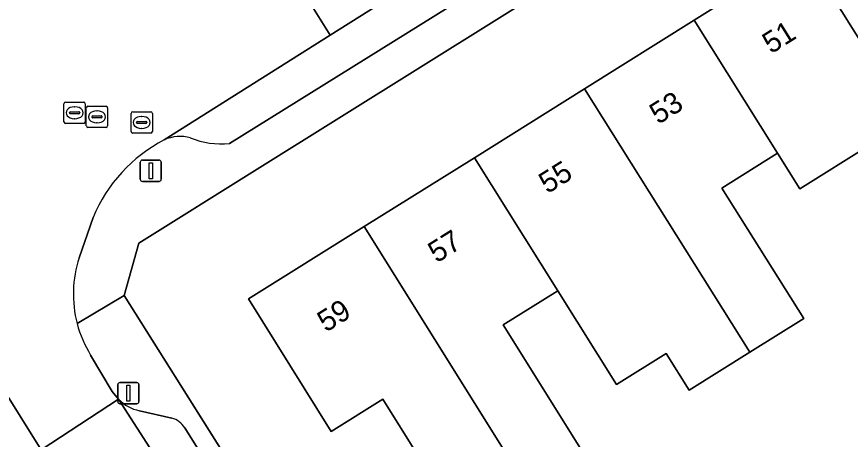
# Model space of a CAD drawing. Extents: x 159352 to 160617, y 385888 to 387323.
# Drawn here: x 159671.45 to 159710.67, y 386028.96 to 386048.83 of the extents above; entities that cross this region are included whole.
import ezdxf

# ---------------------------------------------------------------- set-up
doc = ezdxf.new("R2010")
doc.units = 0
for name, color, linetype in [('IMGEO_Erf', 7, 'Continuous'), ('IMGEO_Kolk', 7, 'Continuous'), ('IMGEO_Lichtmast', 7, 'Continuous'), ('IMGEO_Muur', 7, 'Continuous'), ('IMGEO_Pand', 7, 'Continuous'), ('IMGEO_Pand_nummerreeks', 7, 'Continuous'), ('IMGEO_Parkeervlak_open', 7, 'Continuous'), ('IMGEO_Rijbaan_lokaal_open', 7, 'Continuous'), ('IMGEO_Rioolput', 7, 'Continuous'), ('IMGEO_Voetpad_open', 7, 'Continuous')]:
    doc.layers.add(name, color=color, linetype=linetype)

msp = doc.modelspace()

# ---------------------------------------------------------------- linework, layer by layer
at = {"layer": 'IMGEO_Erf'}
msp.add_lwpolyline([(159733.186, 386035.211), (159730.405, 386039.383), (159739.998, 386045.377), (159726.053, 386067.427), (159724.652, 386067.823), (159682.76, 386041.661), (159677.195, 386038.177), (159676.499, 386035.726), (159692.861, 386009.756), (159693.588, 386010.224), (159695.905, 386011.714), (159692.99, 386016.431), (159699.422, 386020.406), (159702.337, 386015.688), (159707.722, 386019.015), (159705.988, 386021.823), (159710.701, 386024.734), (159712.435, 386021.927)], close=True, dxfattribs=at)
for points in [[(159692.572, 386024.604), (159688.668, 386030.843), (159686.251, 386029.331), (159682.354, 386035.559), (159687.801, 386038.964), (159692.982, 386042.203), (159698.161, 386045.441), (159703.328, 386048.671), (159708.502, 386051.905), (159713.682, 386055.143)], [(159711.6, 386042.813), (159708.294, 386040.745), (159707.246, 386042.417), (159704.617, 386040.772), (159708.473, 386034.64), (159705.947, 386033.06), (159703.085, 386031.27), (159701.997, 386033), (159699.669, 386031.543), (159696.906, 386035.948), (159694.342, 386034.344), (159698.765, 386027.275)]]:
    msp.add_lwpolyline(points, dxfattribs=at)
at = {"layer": 'IMGEO_Kolk'}
for p, q in [((159673.674, 386043.887), (159673.674, 386044.739)), ((159673.749, 386044.813), (159674.601, 386044.813)), ((159674.162, 386044.593), (159674.187, 386044.593)), ((159674.675, 386044.739), (159674.675, 386043.887)), ((159673.933, 386044.307), (159673.933, 386044.319)), ((159674.371, 386044.27), (159673.973, 386044.27)), ((159673.976, 386044.356), (159674.374, 386044.356)), ((159674.417, 386044.319), (159674.417, 386044.307)), ((159674.601, 386043.813), (159673.749, 386043.813)), ((159674.185, 386044.033), (159674.16, 386044.033))]:
    msp.add_line(p, q, dxfattribs=at)
for points in [[(159673.674, 386043.887), (159673.674, 386044.739)], [(159673.749, 386044.813), (159674.601, 386044.813)], [(159674.675, 386044.739), (159674.675, 386043.887)], [(159674.601, 386043.813), (159673.749, 386043.813)]]:
    msp.add_lwpolyline(points, dxfattribs=at)
for centre, radius, start, end in [((159673.751, 386044.737), 0.0765, 91.552, 178.448), ((159673.751, 386044.737), 0.0765, 91.552, 178.448), ((159674.599, 386044.737), 0.0765, 1.552, 88.448), ((159674.599, 386044.737), 0.0765, 1.552, 88.448), ((159673.973, 386044.316), 0.0403, 85.8775, 175.7526), ((159673.97, 386044.306), 0.0366, 178.938, 274.7102), ((159674.374, 386044.313), 0.043, 264.8664, 352.4533), ((159674.378, 386044.318), 0.0386, 1.7309, 96.639), ((159673.751, 386043.889), 0.0765, 181.552, 268.448), ((159673.751, 386043.889), 0.0765, 181.552, 268.448), ((159674.599, 386043.889), 0.0765, 271.552, 358.448), ((159674.599, 386043.889), 0.0765, 271.552, 358.448)]:
    msp.add_arc(centre, radius, start, end, dxfattribs=at)
for centre, major_axis, ratio, start_param, end_param in [((159674.161, 386044.313), (-0.387, 0.002), 0.722429, 4.712389, 7.853982), ((159674.186, 386044.313), (-0.39, 0.002), 0.717154, 1.570796, 4.712389)]:
    msp.add_ellipse(centre, major_axis=major_axis, ratio=ratio, start_param=start_param, end_param=end_param, dxfattribs=at)
at = {"layer": 'IMGEO_Lichtmast'}
for p, q in [((159677.262, 386041.187), (159677.262, 386041.987)), ((159677.262, 386041.987), (159677.262, 386041.187)), ((159677.362, 386042.087), (159678.152, 386042.087)), ((159678.152, 386042.087), (159677.362, 386042.087)), ((159678.252, 386041.987), (159678.252, 386041.187)), ((159678.252, 386041.187), (159678.252, 386041.987)), ((159678.152, 386041.087), (159677.362, 386041.087)), ((159677.362, 386041.087), (159678.152, 386041.087)), ((159676.307, 386031.632), (159677.097, 386031.632)), ((159677.097, 386031.632), (159676.307, 386031.632)), ((159676.207, 386030.732), (159676.207, 386031.532)), ((159676.207, 386031.532), (159676.207, 386030.732)), ((159677.197, 386031.532), (159677.197, 386030.732)), ((159677.197, 386030.732), (159677.197, 386031.532)), ((159677.097, 386030.632), (159676.307, 386030.632)), ((159676.307, 386030.632), (159677.097, 386030.632))]:
    msp.add_line(p, q, dxfattribs=at)
for points in [[(159677.682, 386041.962), (159677.832, 386041.962), (159677.832, 386041.212), (159677.682, 386041.212), (159677.682, 386041.962)], [(159676.627, 386031.507), (159676.777, 386031.507), (159676.777, 386030.757), (159676.627, 386030.757), (159676.627, 386031.507)]]:
    msp.add_lwpolyline(points, dxfattribs=at)
for centre, start, end in [((159677.362, 386041.987), 90, 180), ((159677.362, 386041.987), 90, 180), ((159678.152, 386041.987), 0, 90), ((159678.152, 386041.987), 360, 90), ((159677.362, 386041.187), 180, 270), ((159677.362, 386041.187), 180, 270), ((159678.152, 386041.187), 270, 0), ((159678.152, 386041.187), 270, 0), ((159676.307, 386031.532), 90, 180), ((159676.307, 386031.532), 90, 180), ((159677.097, 386031.532), 0, 90), ((159677.097, 386031.532), 360, 90), ((159676.307, 386030.732), 180, 270), ((159676.307, 386030.732), 180, 270), ((159677.097, 386030.732), 270, 0), ((159677.097, 386030.732), 270, 0)]:
    msp.add_arc(centre, 0.1, start, end, dxfattribs=at)
at = {"layer": 'IMGEO_Muur'}
msp.add_lwpolyline([(159676.499, 386035.726), (159692.838, 386009.794)], dxfattribs=at)
at = {"layer": 'IMGEO_Pand'}
for points in [[(159713.682, 386055.143), (159708.502, 386051.905), (159713.466, 386043.98), (159713.984, 386043.152), (159713.74, 386042.999), (159715.63, 386039.982), (159717.73, 386041.298), (159715.841, 386044.315), (159719.171, 386046.4)], [(159708.502, 386051.905), (159703.328, 386048.671), (159707.246, 386042.417), (159708.294, 386040.745), (159711.6, 386042.813), (159715.372, 386036.791), (159716.992, 386037.806), (159715.63, 386039.982), (159713.74, 386042.999), (159713.984, 386043.152), (159713.466, 386043.98)], [(159703.328, 386048.671), (159698.161, 386045.441), (159705.947, 386033.06), (159708.473, 386034.64), (159704.617, 386040.772), (159707.246, 386042.417)], [(159696.906, 386035.948), (159699.669, 386031.543), (159701.997, 386033), (159703.085, 386031.27), (159705.947, 386033.06), (159698.161, 386045.441), (159692.982, 386042.203)], [(159692.982, 386042.203), (159687.801, 386038.964), (159696.144, 386025.636), (159698.765, 386027.275), (159694.342, 386034.344), (159696.906, 386035.948)], [(159687.801, 386038.964), (159682.354, 386035.559), (159686.251, 386029.331), (159688.668, 386030.843), (159692.572, 386024.604), (159695.412, 386026.381), (159695.953, 386025.516), (159696.144, 386025.636)]]:
    msp.add_lwpolyline(points, close=True, dxfattribs=at)
at = {"layer": 'IMGEO_Parkeervlak_open'}
for points in [[(159717.543, 386067.695), (159686.194, 386047.956), (159678.382, 386043.037)], [(159681.467, 386042.865), (159702.746, 386056.105), (159715.811, 386064.272)], [(159676.243, 386030.847), (159688.08, 386012.469)], [(159678.751, 386029.956), (159677.22, 386030.307)], [(159688.07, 386015.556), (159679.356, 386029.499)]]:
    msp.add_lwpolyline(points, dxfattribs=at)
for centre, radius, start, end in [((159679.137, 386041.369), 1.831, 74.7207, 114.3387), ((159681.107, 386046.862), 4.013, 248.2307, 275.1446), ((159677.576, 386032.105), 1.832, 223.336, 258.8041), ((159678.504, 386029), 0.987, 30.3488, 75.5185)]:
    msp.add_arc(centre, radius, start, end, dxfattribs=at)
at = {"layer": 'IMGEO_Rijbaan_lokaal_open'}
for points in [[(159684.747, 386051.268), (159684.308, 386050.988), (159686.194, 386047.956), (159717.543, 386067.695), (159717.747, 386067.827), (159715.89, 386070.74), (159715.668, 386070.601)], [(159729.606, 385937.026), (159733.392, 385939.433), (159733.253, 385939.657), (159690.064, 386009.27), (159688.08, 386012.469), (159676.243, 386030.847), (159672.6, 386028.467), (159676.012, 386023.063), (159685.883, 386007.217), (159686.951, 386005.519), (159689.128, 386002.021), (159729.51, 385937.17)]]:
    msp.add_lwpolyline(points, close=True, dxfattribs=at)
for points in [[(159678.382, 386043.037), (159686.194, 386047.956), (159684.308, 386050.988), (159683.792, 386050.662), (159682.262, 386049.724)], [(159674.391, 386037.496), (159675.043, 386039.396)], [(159670.612, 386031.633), (159672.6, 386028.467), (159676.243, 386030.847), (159675.949, 386031.202), (159674.928, 386032.924)]]:
    msp.add_lwpolyline(points, dxfattribs=at)
for centre, radius, start, end in [((159681.753, 386036.594), 7.271, 117.6176, 157.3373), ((159679.567, 386035.786), 5.451, 161.7188, 194.6875), ((159679.547, 386035.779), 5.43, 194.6635, 211.715)]:
    msp.add_arc(centre, radius, start, end, dxfattribs=at)
at = {"layer": 'IMGEO_Rioolput'}
for p, q in [((159674.726, 386043.696), (159674.726, 386044.548)), ((159674.801, 386044.622), (159675.653, 386044.622)), ((159675.727, 386044.548), (159675.727, 386043.696)), ((159674.985, 386044.116), (159674.985, 386044.128)), ((159675.028, 386044.165), (159675.426, 386044.165)), ((159675.214, 386044.402), (159675.239, 386044.402)), ((159675.469, 386044.128), (159675.469, 386044.116)), ((159676.831, 386043.433), (159676.831, 386044.285)), ((159676.906, 386044.359), (159677.758, 386044.359)), ((159677.319, 386044.139), (159677.344, 386044.139)), ((159677.832, 386044.285), (159677.832, 386043.433)), ((159675.423, 386044.079), (159675.025, 386044.079)), ((159675.237, 386043.842), (159675.212, 386043.842)), ((159677.09, 386043.853), (159677.09, 386043.865)), ((159677.528, 386043.816), (159677.13, 386043.816)), ((159677.133, 386043.902), (159677.531, 386043.902)), ((159677.574, 386043.865), (159677.574, 386043.853)), ((159675.653, 386043.622), (159674.801, 386043.622)), ((159677.758, 386043.359), (159676.906, 386043.359)), ((159677.342, 386043.579), (159677.317, 386043.579))]:
    msp.add_line(p, q, dxfattribs=at)
for points in [[(159674.726, 386043.696), (159674.726, 386044.548)], [(159674.801, 386044.622), (159675.653, 386044.622)], [(159675.727, 386044.548), (159675.727, 386043.696)], [(159676.831, 386043.433), (159676.831, 386044.285)], [(159676.906, 386044.359), (159677.758, 386044.359)], [(159677.832, 386044.285), (159677.832, 386043.433)], [(159675.653, 386043.622), (159674.801, 386043.622)], [(159677.758, 386043.359), (159676.906, 386043.359)]]:
    msp.add_lwpolyline(points, dxfattribs=at)
for centre, radius, start, end in [((159674.803, 386044.546), 0.0765, 91.552, 178.448), ((159674.803, 386044.546), 0.0765, 91.552, 178.448), ((159675.651, 386044.546), 0.0765, 1.552, 88.448), ((159675.651, 386044.546), 0.0765, 1.552, 88.448), ((159675.025, 386044.125), 0.0403, 85.8775, 175.7526), ((159675.022, 386044.115), 0.0366, 178.938, 274.7102), ((159675.426, 386044.122), 0.043, 264.8664, 352.4533), ((159675.43, 386044.127), 0.0386, 1.7309, 96.639), ((159676.908, 386044.283), 0.0765, 91.552, 178.448), ((159676.908, 386044.283), 0.0765, 91.552, 178.448), ((159677.756, 386044.283), 0.0765, 1.552, 88.448), ((159677.756, 386044.283), 0.0765, 1.552, 88.448), ((159677.13, 386043.862), 0.0403, 85.8775, 175.7526), ((159677.127, 386043.852), 0.0366, 178.938, 274.7102), ((159677.531, 386043.859), 0.043, 264.8664, 352.4533), ((159677.535, 386043.864), 0.0386, 1.7309, 96.639), ((159674.803, 386043.698), 0.0765, 181.552, 268.448), ((159674.803, 386043.698), 0.0765, 181.552, 268.448), ((159675.651, 386043.698), 0.0765, 271.552, 358.448), ((159675.651, 386043.698), 0.0765, 271.552, 358.448), ((159676.908, 386043.435), 0.0765, 181.552, 268.448), ((159676.908, 386043.435), 0.0765, 181.552, 268.448), ((159677.756, 386043.435), 0.0765, 271.552, 358.448), ((159677.756, 386043.435), 0.0765, 271.552, 358.448)]:
    msp.add_arc(centre, radius, start, end, dxfattribs=at)
for centre, major_axis, ratio, start_param, end_param in [((159675.213, 386044.122), (-0.387, 0.002), 0.722429, 4.712389, 7.853982), ((159675.238, 386044.122), (-0.39, 0.002), 0.717154, 1.570796, 4.712389), ((159677.318, 386043.859), (-0.387, 0.002), 0.722429, 4.712389, 7.853982), ((159677.343, 386043.859), (-0.39, 0.002), 0.717154, 1.570796, 4.712389)]:
    msp.add_ellipse(centre, major_axis=major_axis, ratio=ratio, start_param=start_param, end_param=end_param, dxfattribs=at)
at = {"layer": 'IMGEO_Voetpad_open'}
for points in [[(159674.294, 386034.404), (159676.499, 386035.726), (159677.195, 386038.177), (159682.76, 386041.661), (159724.652, 386067.823)], [(159715.811, 386064.272), (159702.746, 386056.105), (159681.467, 386042.865)], [(159675.043, 386039.396), (159674.391, 386037.496)], [(159676.499, 386035.726), (159674.294, 386034.404)], [(159733.253, 385939.657), (159733.392, 385939.433), (159733.652, 385939.014), (159736.793, 385940.979), (159724.622, 385960.426), (159722.539, 385963.769), (159695.653, 386006.911), (159694.532, 386008.709), (159693.588, 386010.224), (159692.861, 386009.756), (159676.499, 386035.726)], [(159674.928, 386032.924), (159675.949, 386031.202), (159676.243, 386030.847)], [(159689.128, 386002.021), (159688.743, 386001.782), (159686.576, 386005.278), (159686.951, 386005.519), (159685.883, 386007.217), (159685.522, 386006.976), (159675.629, 386022.83), (159676.012, 386023.063), (159672.6, 386028.467), (159670.612, 386031.633)], [(159677.22, 386030.307), (159678.751, 386029.956)], [(159679.356, 386029.499), (159688.07, 386015.556)]]:
    msp.add_lwpolyline(points, dxfattribs=at)
for centre, radius, start, end in [((159681.753, 386036.594), 7.271, 117.6176, 157.3373), ((159679.137, 386041.369), 1.831, 74.7207, 114.3387), ((159681.107, 386046.862), 4.013, 248.2307, 275.1446), ((159679.567, 386035.786), 5.451, 161.7188, 194.6875), ((159679.547, 386035.779), 5.43, 194.6635, 211.715), ((159677.576, 386032.105), 1.832, 223.336, 258.8041), ((159678.504, 386029), 0.987, 30.3488, 75.5185)]:
    msp.add_arc(centre, radius, start, end, dxfattribs=at)

# ---------------------------------------------------------------- texts
at = {"layer": 'IMGEO_Pand_nummerreeks'}
for s, p in [('51', (159706.935, 386047.058)), ('53', (159701.629, 386043.741)), ('55', (159696.419, 386040.483)), ('57', (159691.208, 386037.226)), ('59', (159685.998, 386033.969))]:
    msp.add_text(s, height=1, rotation=32.0112, dxfattribs=at).set_placement(p)

doc.saveas('drawing.dxf')
